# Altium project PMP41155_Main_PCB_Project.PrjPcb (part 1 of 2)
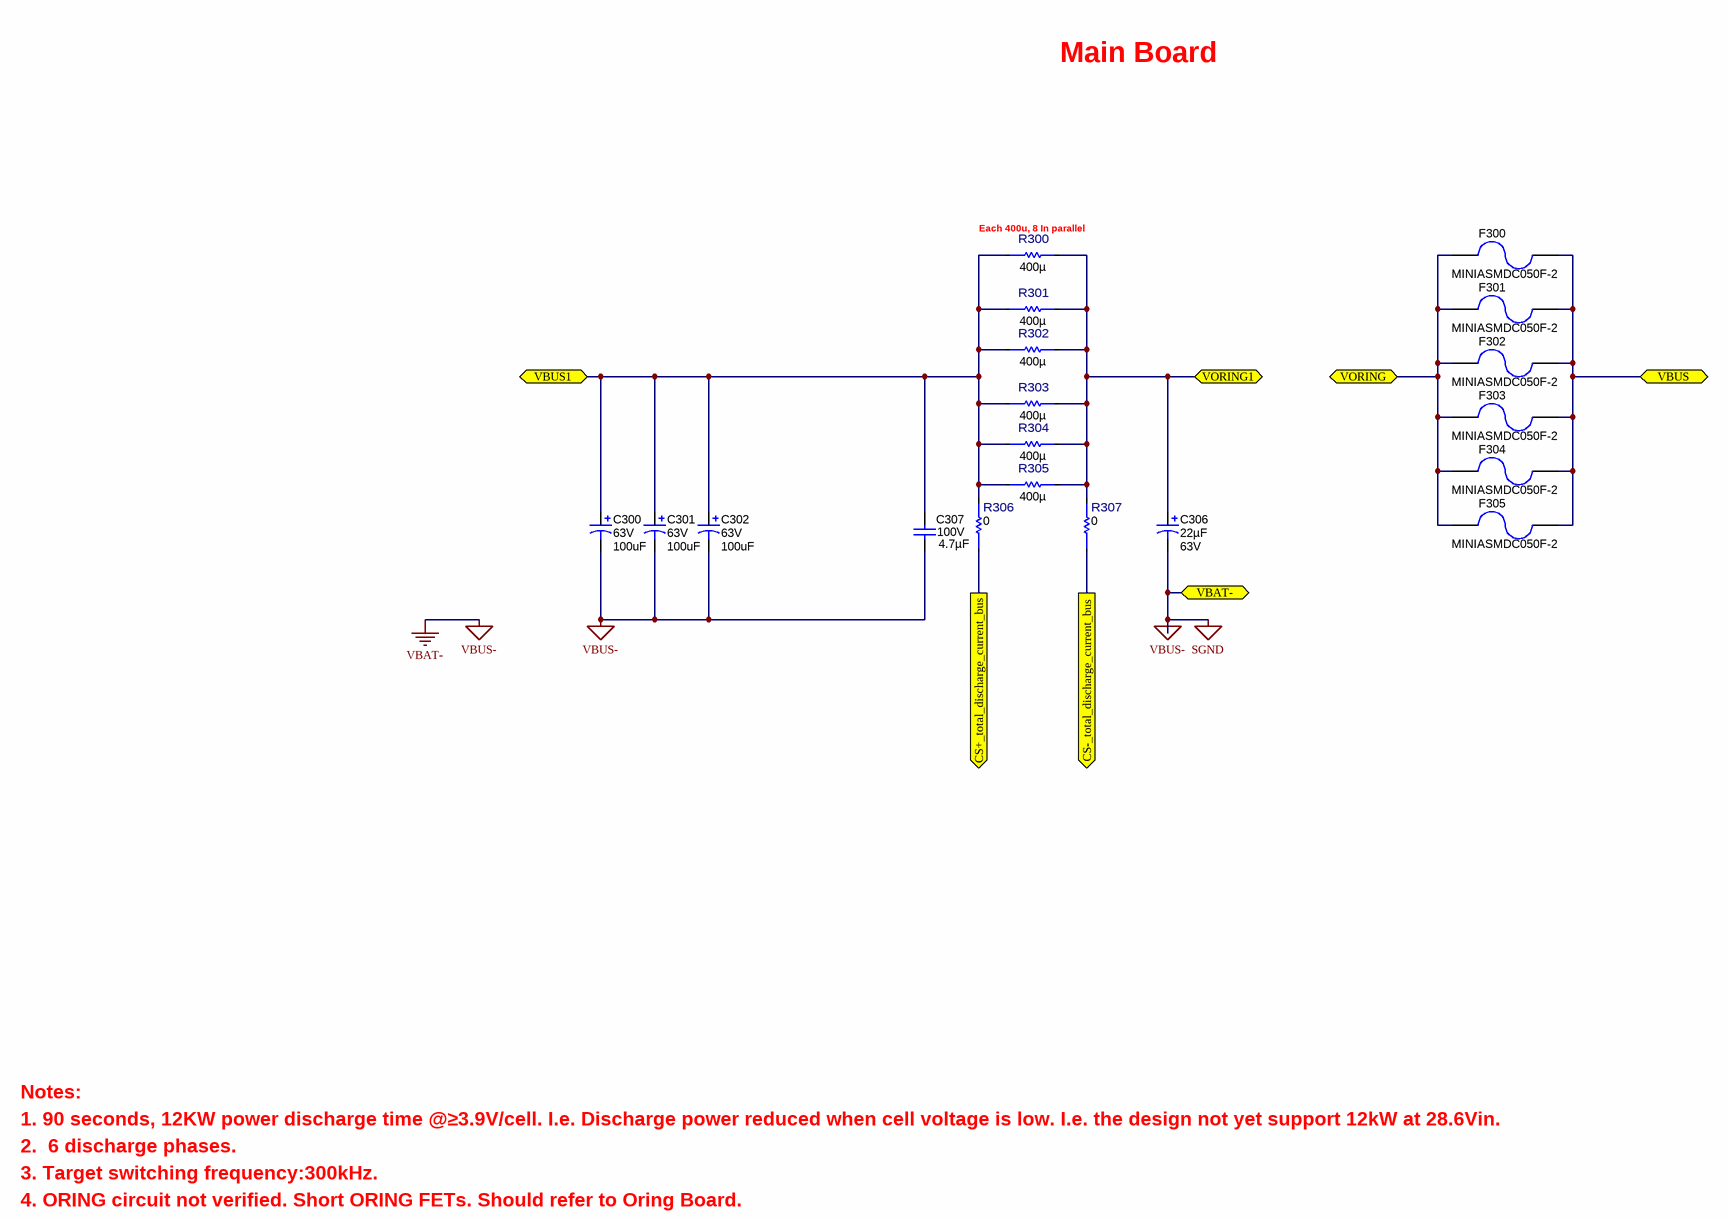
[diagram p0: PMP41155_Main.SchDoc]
CopyrightYear: 2025; PCB_Layout: Richard Yin; PCB_Rev: E1; PRJ_Customer: Public Release; PRJ_Engineer: Richard Yin; PRJ_Number: PMP41155_Main; PRJ_Title: Change in menu Project|Project Options|Parameters; SCH_Rev: E1; TechSupport: http://www.ti.com/support; TID: N/A
5 sheets, 249 parts. Net scope: flat (ports and power ports of the same name join across sheets).
Board file: PMP41155_Main.PcbDoc
Sheets:
  PMP41155_Main.SchDoc
  PMP41155_Main_Control 2.SchDoc
  PMP41155_Main_Control 1.SchDoc
  PMP41155_Main_Control.SchDoc
  PMP41155_Main_Connection.SchDoc

## Sheet PMP41155_Main.SchDoc
size 431 x 279 mm; Date: Not shown in title block; ApprovedBy: Not shown in title block; CheckedBy: Not shown in title block; Author: Not shown in title block; CompanyName: Not shown in title block; Engineer: Not shown in title block; Organization: Not shown in title block; Address1: Not shown in title block; Address2: Not shown in title block; Address3: Not shown in title block; Address4: Not shown in title block; DocumentNumber: 1; Revision: Use project parameter SCH_Rev; SheetNumber: 1; SheetTotal: 5; PageSetup: Record=PageOptions¦CenterHorizontal=True¦CenterVertical=True¦PrintScale=1.00¦XCorrection=1.00¦YCorrection=1.00¦PrintKind=0¦BorderSize=5000000¦LeftOffset=0¦BottomOffset=0¦Orientation=2¦PaperLength=1000¦PaperWidth=1000¦Scale=100¦PaperSource=15¦PrintQuality=600¦MediaType=1¦DitherType=10¦PaperKind=Letter¦PrintScaleMode=1

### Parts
C300  VDC_V: 63V  ValueDisplayed: 100uF  [CAPSMT_62_KE0]  (hidden comment: EMVY630ATR101MKE0S)
C301  VDC_V: 63V  ValueDisplayed: 100uF  [CAPSMT_62_KE0]  (hidden comment: EMVY630ATR101MKE0S)
C302  VDC_V: 63V  ValueDisplayed: 100uF  [CAPSMT_62_KE0]  (hidden comment: EMVY630ATR101MKE0S)
C306  ValueDisplayed: 22µF  Value2: 63V  [SM_RADIAL_D]  (hidden comment: 63PFV22M6.3X8)
C307  ValueDisplayed: 4.7µF  Value2: 100V  [1206_180]  (hidden comment: GRJ31CC72A475KE01L)
F300  MINIASMDC050F-2  [1812]
F301  MINIASMDC050F-2  [1812]
F302  MINIASMDC050F-2  [1812]
F303  MINIASMDC050F-2  [1812]
F304  MINIASMDC050F-2  [1812]
F305  MINIASMDC050F-2  [1812]
R300  value 400µ  [FP-PU3921FKNP90U4L_3921-MFG]  (hidden comment: PU3921FKNP90U4L)
R301  value 400µ  [FP-PU3921FKNP90U4L_3921-MFG]  (hidden comment: PU3921FKNP90U4L)
R302  value 400µ  [FP-PU3921FKNP90U4L_3921-MFG]  (hidden comment: PU3921FKNP90U4L)
R303  value 400µ  [FP-PU3921FKNP90U4L_3921-MFG]  (hidden comment: PU3921FKNP90U4L)
R304  value 400µ  [FP-PU3921FKNP90U4L_3921-MFG]  (hidden comment: PU3921FKNP90U4L)
R305  value 400µ  [FP-PU3921FKNP90U4L_3921-MFG]  (hidden comment: PU3921FKNP90U4L)
R306  Res_ohm: 0  [FP-RC0603JR-130RP_0603-MFG]  (hidden comment: RC0603JR-130RP)
R307  Res_ohm: 0  [FP-RC0603JR-130RP_0603-MFG]  (hidden comment: RC0603JR-130RP)

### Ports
CS+_total_discharge_current_bus (out), CS-_total_discharge_current_bus (out), VBAT- (bidir), VBUS1 (bidir), VBUS (bidir), VORING1 (bidir), VORING (bidir)

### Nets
SGND: C300.2(-) C301.2(-) C302.2(-) C306.2(-) C307.2 ; port VBAT-  [also labelled VBAT-, VBUS-]
CS+_total_discharge_current_bus: R306.1 ; port CS+_total_discharge_current_bus
CS-_total_discharge_current_bus: R307.1 ; port CS-_total_discharge_current_bus
VBUS: F300.1 F301.1 F302.1 F303.1 F304.1 F305.1 ; port VBUS
VBUS1: C300.1(+) C301.1(+) C302.1(+) C307.1 R300.1 R301.1 R302.1 R303.1 R304.1 R305.1 R306.2 ; port VBUS1
VORING: F300.2 F301.2 F302.2 F303.2 F304.2 F305.2 ; port VORING
VORING1: C306.1(+) R300.2 R301.2 R302.2 R303.2 R304.2 R305.2 R307.2 ; port VORING1

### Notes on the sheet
- Main Board
- (near R300) Each 400u, 8 In parallel
- Notes:
- 2.  6 discharge phases.
- 1. 90 seconds, 12KW power discharge time @≥3.9V/cell. I.e. Discharge power reduced when cell voltage is low. I.e. the design not yet support 12kW at 28.6Vin.
- 3. Target switching frequency:300kHz.
- 4. ORING circuit not verified. Short ORING FETs. Should refer to Oring Board.

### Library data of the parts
C300-C302 = CMP-0011370-2: CAP, AL, 100 uF, 63 V, +/- 20%, 0.19 ohm, SMD; Manufacturer: Chemi-Con; TaMin_C: -55°C; ESR_ohm: 0.19; Polarized: Y; SizeAreaWB_mm2: 225; U/M: EA; Value: 100uF; TaMax_C: 105°C; SizeZ_mm: 13.5; SizeX_mm: 13; Cap_Case: KE0; SizeArea_mm2: 169; CompType: Capacitor; Cap_F: 100µF; IRMS_A: 500mA; AEC Category: Q200
C306 = EEE-FK1H220P: CAP ALUM POLY HYB 22UF 63V SMD; Manufacturer: Rubycon; Polarized: Y; CompType: Capacitor; Cap_F: 0.000022; Tolerance_%: 20; Value1: 0.88 ohm; VDC_V: 63; Cap_Case: D; SizeAreaWB_mm2: 84.28; SizeArea_mm2: 51.48; SizeX_mm: 7.8; SizeY_mm: 6.6; SizeZ_mm: 5.4; Green_Lifecycle: Active; Green_REACh: Passed
C307 = C3216X6S1H475K160AB: CAP CER 4.7UF 100V X7S 1206; Polarized: N; CompType: Capacitor; U/M: EA; Cap_F: 0.0000047; Tolerance_%: 10; VDC_V: 100; TaMin_C: -55; TaMax_C: 105; Cap_Case: 1206; SizeArea_mm2: 5.12; SizeAreaWB_mm2: 10.92; SizeX_mm: 3.2; SizeY_mm: 1.6; SizeZ_mm: 1.8; AEC Category: Q200
F300-F305 = CMP-0003593-3: Fuse, Resettable, 100 A, 24 VDC, SMD; Manufacturer: Littelfuse; Irating_A: 100A; SizeAreaWB_mm2: 23.1; SizeZ_mm: 1.35; SizeX_mm: 4.5; SizeY_mm: 3.2; SizeArea_mm2: 14.4; VDC_V: 24V
R300-R305 = CMP-0096319-1: 400 µOhms ±1% 9W Chip Resistor Nonstandard Automotive AEC-Q200, Current Sense, Moisture Resistant Metal Element; Manufacturer: YAGEO; AEC Qualified: Yes; TempCo: 175ppm/°C; SizeZ_mm: 1.81mm; AEC Grade: Grade 0; Standoff Height: 0.37mm
R306 R307 = CMP-0120804-1: Resistor Thick Film 0603 Jumper 0 Ohm ±5% 1/10W Molded Paper T/R; Manufacturer: Yageo; AEC Qualified: No; Power_W: 100mW; SizeZ_mm: 0.55mm; VDC_V: 75V; Value: 0

## Sheet PMP41155_Main_Control 2.SchDoc
size 431 x 279 mm; Date: Not shown in title block; ApprovedBy: Not shown in title block; CheckedBy: Not shown in title block; Author: Not shown in title block; CompanyName: Not shown in title block; Engineer: Not shown in title block; Organization: Not shown in title block; Address1: Not shown in title block; Address2: Not shown in title block; Address3: Not shown in title block; Address4: Not shown in title block; DocumentNumber: 2; Revision: Use project parameter SCH_Rev; SheetNumber: 2; SheetTotal: 5; PageSetup: Record=PageOptions¦CenterHorizontal=True¦CenterVertical=True¦PrintScale=1.00¦XCorrection=1.00¦YCorrection=1.00¦PrintKind=0¦BorderSize=5000000¦LeftOffset=0¦BottomOffset=0¦Orientation=2¦PaperLength=1000¦PaperWidth=1000¦Scale=100¦PaperSource=15¦PrintQuality=600¦MediaType=1¦DitherType=10¦PaperKind=Letter¦PrintScaleMode=1
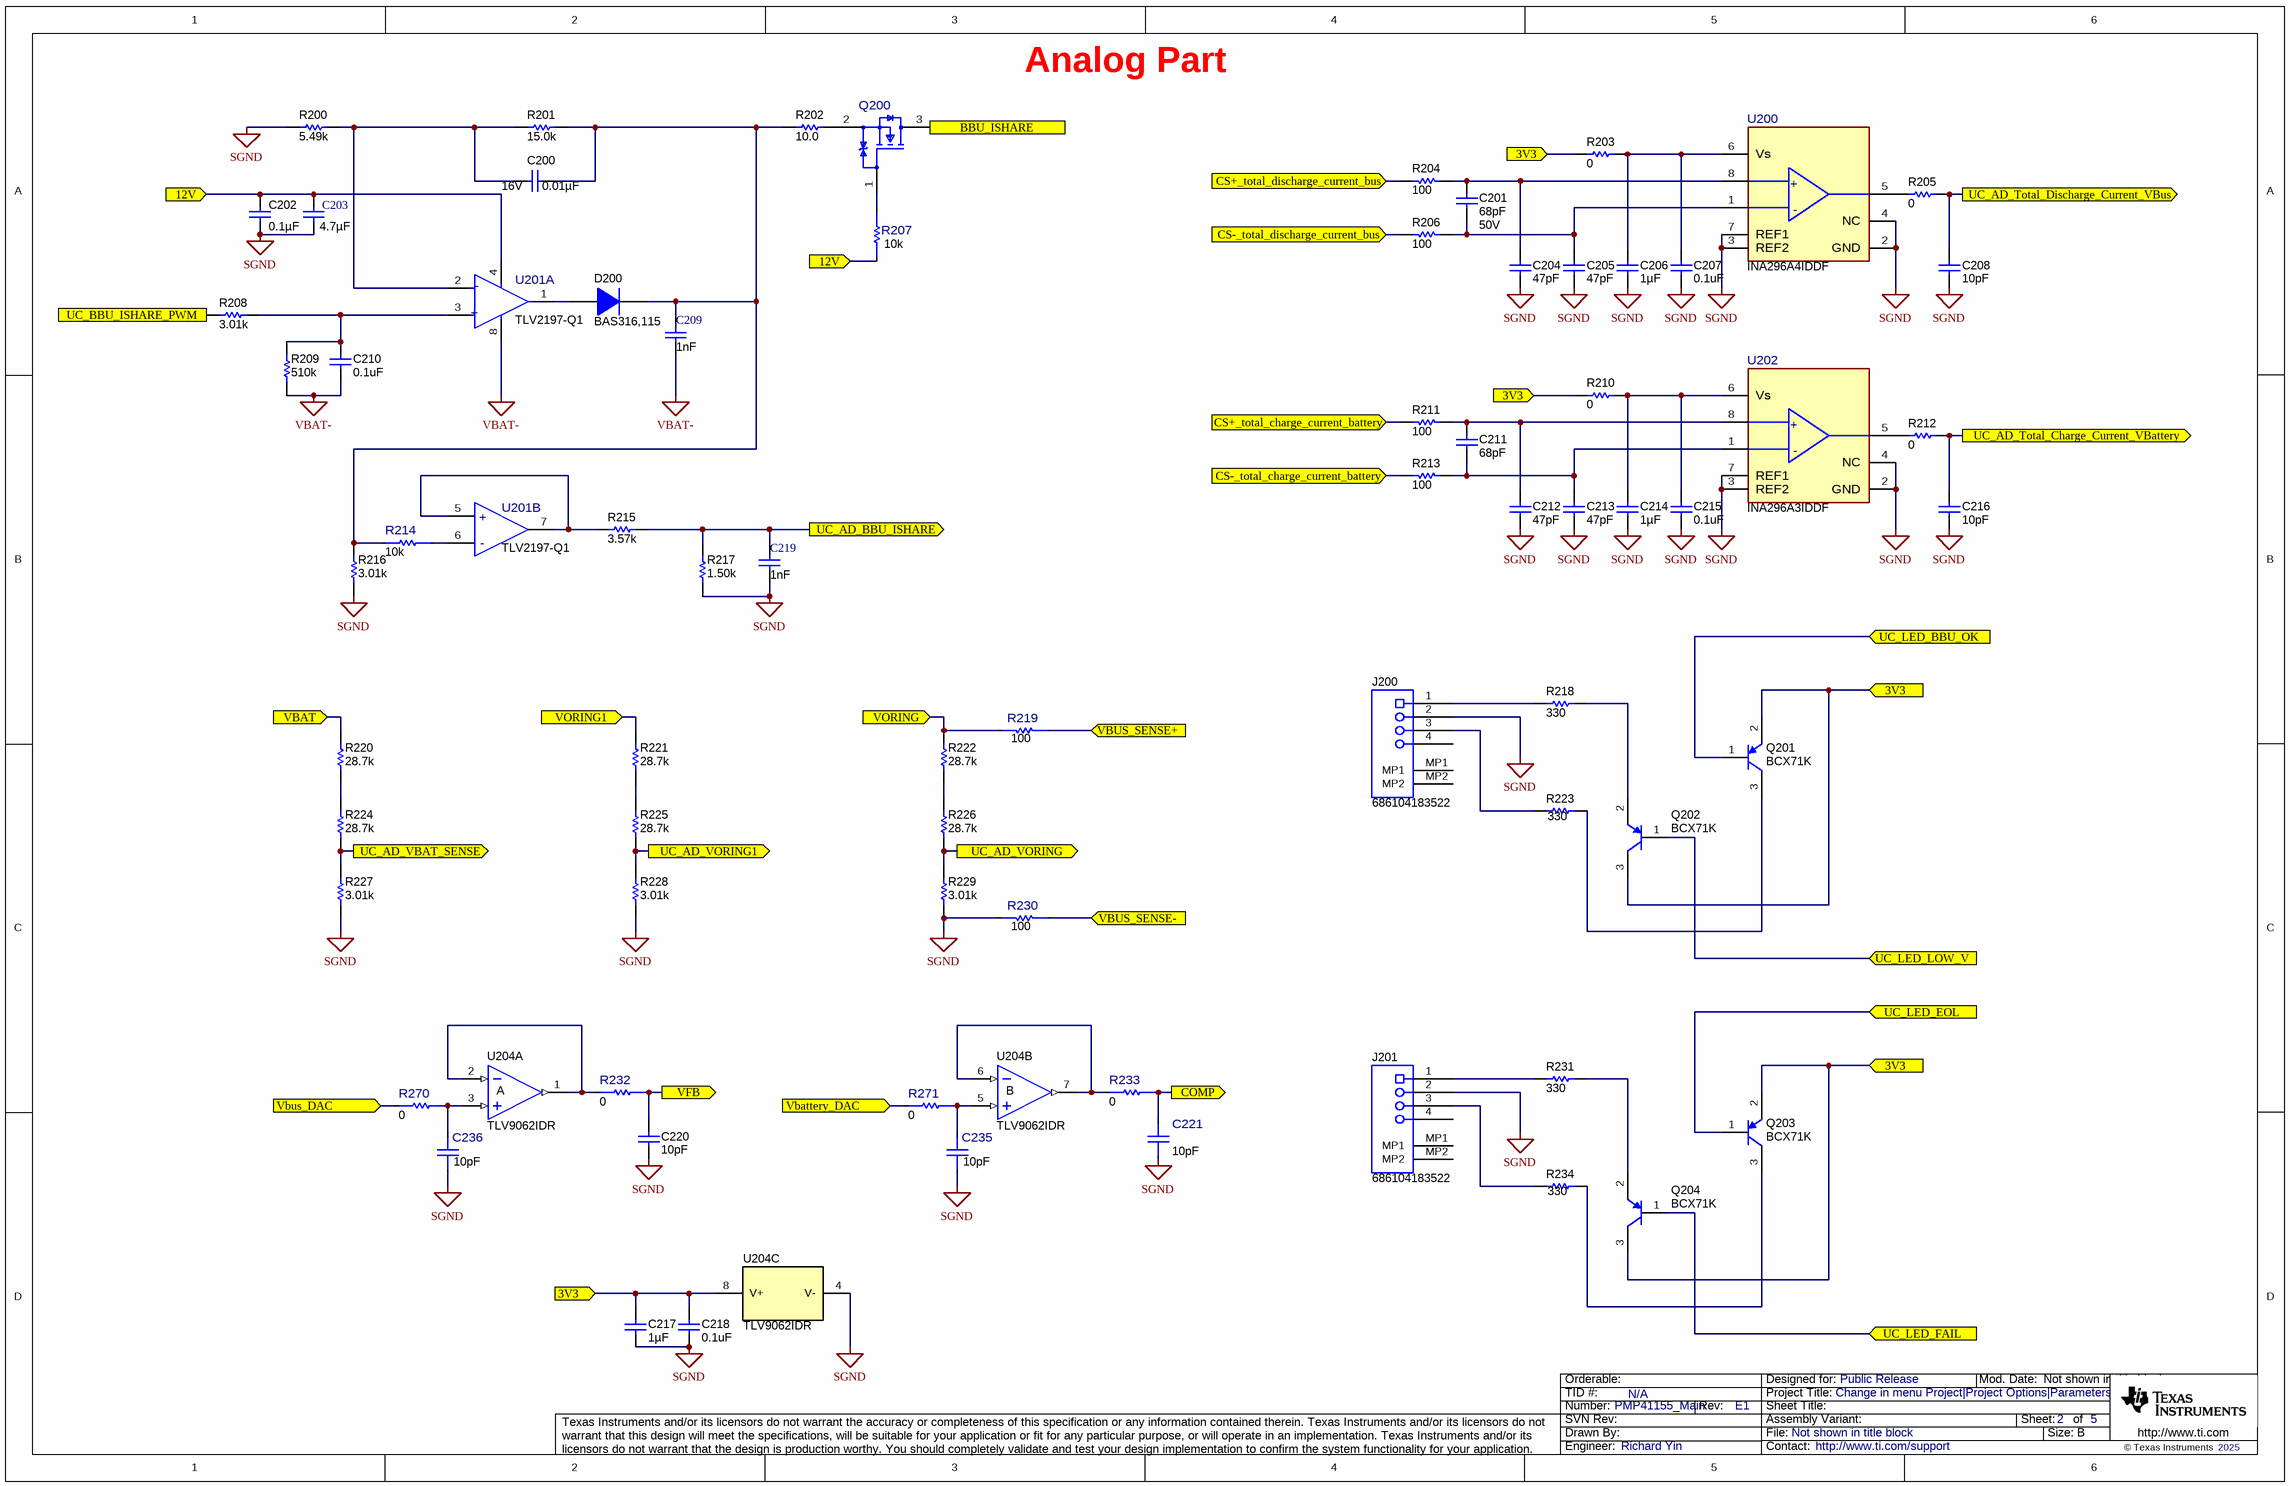
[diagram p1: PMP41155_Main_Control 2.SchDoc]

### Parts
C200  VDC_V: 16V  ValueDisplayed: 0.01µF  [0402]  (hidden comment: C0402C103K4RACTU)
C201  ValueDisplayed: 68pF  Value2: 50V  [0603]  (hidden comment: 06035A680JAT2A)
C202  ValueDisplayed: 0.1µF  [0603]  (hidden comment: 0603YC104K4T4A)
C203  Cap_F: 4.7µF  [WCAP-CSGP_0805_L2W1.25H1.25]  (hidden comment: 885012107013)
C204  ValueDisplayed: 47pF  [0402]  (hidden comment: GRM1555C1H470FA01D)
C205  ValueDisplayed: 47pF  [0402]  (hidden comment: GRM1555C1H470FA01D)
C206  ValueDisplayed: 1µF  [0603]  (hidden comment: C1608X7R1C105K080AC)
C207  ValueDisplayed: 0.1uF  [0402]  (hidden comment: GRM155R70J104KA01D)
C208  ValueDisplayed: 10pF  [0603]  (hidden comment: C0603C100F5GAC7867)
C209  Cap_F: 1nF  [WCAP-CSGP_0402_L1W0.5H0.5]  (hidden comment: 885012205061)
C210  ValueDisplayed: 0.1uF  [0402]  (hidden comment: GRM155R70J104KA01D)
C211  ValueDisplayed: 68pF  [0603]  (hidden comment: 06035A680JAT2A)
C212  ValueDisplayed: 47pF  [0402]  (hidden comment: GRM1555C1H470FA01D)
C213  ValueDisplayed: 47pF  [0402]  (hidden comment: GRM1555C1H470FA01D)
C214  ValueDisplayed: 1µF  [0603]  (hidden comment: C1608X7R1C105K080AC)
C215  ValueDisplayed: 0.1uF  [0402]  (hidden comment: GRM155R70J104KA01D)
C216  ValueDisplayed: 10pF  [0603]  (hidden comment: C0603C100F5GAC7867)
C217  Cap_F: 1µF  [0603]  (hidden comment: GCM188R71C105KA64J)
C218  ValueDisplayed: 0.1uF  [0402]  (hidden comment: GRM155R70J104KA01D)
C219  Cap_F: 1nF  [WCAP-CSGP_0402_L1W0.5H0.5]  (hidden comment: 885012205061)
C220  ValueDisplayed: 10pF  [0603]  (hidden comment: C0603C100F5GAC7867)
C221  ValueDisplayed: 10pF  [FP-06035C100KAT2A_0603-MFG]  (hidden comment: 06035C100KAT2A)
C235  ValueDisplayed: 10pF  [FP-06035C100KAT2A_0603-MFG]  (hidden comment: 06035C100KAT2A)
C236  ValueDisplayed: 10pF  [FP-06035C100KAT2A_0603-MFG]  (hidden comment: 06035C100KAT2A)
D200  BAS316,115  [SOD-323]
J200  686104183522  [Wurth_686104183522]
J201  686104183522  [Wurth_686104183522]
Q200  2N7002KL3A-TP  [FP-2N7002KL3A-TP_DFN3-MFG]  (value not drawn)
Q201  BCX71K  [SOT-23]
Q202  BCX71K  [SOT-23]
Q203  BCX71K  [SOT-23]
Q204  BCX71K  [SOT-23]
R200  ValueDisplayed: 5.49k  [0402]  (hidden comment: CRCW04025K49FKED)
R201  ValueDisplayed: 15.0k  [0402]  (hidden comment: CRCW040215K0FKED)
R202  ValueDisplayed: 10.0  [0402]  (hidden comment: MCR01MZPF10R0)
R203  ValueDisplayed: 0  [0603]  (hidden comment: RC0603JR-070RL)
R204  ValueDisplayed: 100  [0603]  (hidden comment: RC0603FR-07100RL)
R205  ValueDisplayed: 0  [0603]  (hidden comment: RC0603JR-070RL)
R206  ValueDisplayed: 100  [0603]  (hidden comment: RC0603FR-07100RL)
R207  Res_ohm: 10k  [FP-ERJ-U02F1002X_0402-MFG]  (hidden comment: ERJ-U02F1002X)
R208  ValueDisplayed: 3.01k  [0402]  (hidden comment: CRCW04023K01FKED)
R209  ValueDisplayed: 510k  [0603]  (hidden comment: RC0603FR-07510KL)
R210  ValueDisplayed: 0  [0603]  (hidden comment: RC0603JR-070RL)
R211  ValueDisplayed: 100  [0603]  (hidden comment: RC0603FR-07100RL)
R212  ValueDisplayed: 0  [0603]  (hidden comment: RC0603JR-070RL)
R213  ValueDisplayed: 100  [0603]  (hidden comment: RC0603FR-07100RL)
R214  Res_ohm: 10k  [FP-ERJ-U02F1002X_0402-MFG]  (hidden comment: ERJ-U02F1002X)
R215  ValueDisplayed: 3.57k  [0402]  (hidden comment: CRCW04023K57FKED)
R216  ValueDisplayed: 3.01k  [0402]  (hidden comment: CRCW04023K01FKED)
R217  ValueDisplayed: 1.50k  [0402]  (hidden comment: ERJ-2RKF1501X)
R218  ValueDisplayed: 330  [0402]  (hidden comment: CRCW0402330RJNED)
R219  Res_ohm: 100  [FP-RK73H1JTTD1000F_0603-MFG]  (hidden comment: RK73H1JTTD1000F)
R220  ValueDisplayed: 28.7k  [0603]  (hidden comment: CRCW060328K7FKEA)
R221  ValueDisplayed: 28.7k  [0603]  (hidden comment: RC0603FR-0728K7L)
R222  ValueDisplayed: 28.7k  [0603]  (hidden comment: CRCW060328K7FKEA)
R223  ValueDisplayed: 330  [0402]  (hidden comment: CRCW0402330RJNED)
R224  ValueDisplayed: 28.7k  [0603]  (hidden comment: CRCW060328K7FKEA)
R225  ValueDisplayed: 28.7k  [0603]  (hidden comment: CRCW060328K7FKEA)
R226  ValueDisplayed: 28.7k  [0603]  (hidden comment: RC0603FR-0728K7L)
R227  ValueDisplayed: 3.01k  [0603]  (hidden comment: CRCW06033K01FKEA)
R228  ValueDisplayed: 3.01k  [0603]  (hidden comment: RT0603BRD073K01L)
R229  ValueDisplayed: 3.01k  [0603]  (hidden comment: RT0603BRD073K01L)
R230  Res_ohm: 100  [FP-RK73H1JTTD1000F_0603-MFG]  (hidden comment: RK73H1JTTD1000F)
R231  ValueDisplayed: 330  [0402]  (hidden comment: CRCW0402330RJNED)
R232  Res_ohm: 0  [FP-RC0603JR-130RP_0603-MFG]  (hidden comment: RC0603JR-130RP)
R233  Res_ohm: 0  [FP-RC0603JR-130RP_0603-MFG]  (hidden comment: RC0603JR-130RP)
R234  ValueDisplayed: 330  [0402]  (hidden comment: CRCW0402330RJNED)
R270  Res_ohm: 0  [FP-RC0603JR-130RP_0603-MFG]  (hidden comment: RC0603JR-130RP)
R271  Res_ohm: 0  [FP-RC0603JR-130RP_0603-MFG]  (hidden comment: RC0603JR-130RP)
U200  INA296A4IDDF  [DDF0008A-MFG]
U201  TLV2197-Q1  [DGK0008A-MFG]  (parts A,B of 2)
U202  INA296A3IDDF  [DDF0008A-MFG]
U204  TLV9062IDR  [D0008A_N]  (parts A,B,C of 3)

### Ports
3V3 (in), 12V (in), BBU_ISHARE (out), COMP (out), CS+_total_charge_current_battery (in), CS+_total_discharge_current_bus (in), CS-_total_charge_current_battery (in), CS-_total_discharge_current_bus (in), UC_AD_BBU_ISHARE (out), UC_AD_Total_Charge_Current_VBattery (out), UC_AD_Total_Discharge_Current_VBus (out), UC_AD_VBAT_SENSE (out), UC_AD_VORING1 (out), UC_AD_VORING (out), UC_BBU_ISHARE_PWM (in), UC_LED_BBU_OK (in), UC_LED_EOL (in), UC_LED_FAIL (in), UC_LED_LOW_V (in), VBAT (in), Vbattery_DAC (in), Vbus_DAC (in), VBUS_SENSE+ (in), VBUS_SENSE- (in), VFB (out), VORING1 (in), VORING (in)

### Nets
SGND: C202.2 C203.1 C204.2 C205.2 C206.2 C207.2 C208.2 C209.1 C210.2 C212.2 C213.2 C214.2 C215.2 C216.2 C217.2 C218.2 C219.1 C220.2 C221.1 C235.1 C236.1 J200.2 J201.2 R200.1 R209.1 R216.1 R217.1 R227.1 R228.1 R229.1 R230.2 U200.2(GND) U200.3(REF2) U200.4(NC) U200.7(REF1) U201.8(V+) U202.2(GND) U202.3(REF2) U202.4(NC) U202.7(REF1) U204.4(V-)  [also labelled VBAT-]
3V3: C217.1 C218.1 Q201.2(E) Q202.3(C) Q203.2(E) Q204.3(C) R203.1 R210.1 U204.8(V+) ; port 3V3
12V: C202.1 C203.2 R207.1 U201.4(V-) ; port 12V
BBU_ISHARE: Q200.3(D) ; port BBU_ISHARE
COMP: C221.2 R233.1 ; port COMP
CS+_total_charge_current_battery: R211.2 ; port CS+_total_charge_current_battery
CS+_total_discharge_current_bus: R204.2 ; port CS+_total_discharge_current_bus
CS-_total_charge_current_battery: R213.2 ; port CS-_total_charge_current_battery
CS-_total_discharge_current_bus: R206.2 ; port CS-_total_discharge_current_bus
UC_AD_BBU_ISHARE: C219.2 R215.2 R217.2 ; port UC_AD_BBU_ISHARE
UC_AD_Total_Charge_Current_VBattery: C216.1 R212.2 ; port UC_AD_Total_Charge_Current_VBattery
UC_AD_Total_Discharge_Current_VBus: C208.1 R205.2 ; port UC_AD_Total_Discharge_Current_VBus
UC_AD_VBAT_SENSE: R224.1 R227.2 ; port UC_AD_VBAT_SENSE
UC_AD_VORING: R226.1 R229.2 ; port UC_AD_VORING
UC_AD_VORING1: R225.1 R228.2 ; port UC_AD_VORING1
UC_BBU_ISHARE_PWM: R208.1 ; port UC_BBU_ISHARE_PWM
UC_LED_BBU_OK: Q201.1(B) ; port UC_LED_BBU_OK
UC_LED_EOL: Q203.1(B) ; port UC_LED_EOL
UC_LED_FAIL: Q204.1(B) ; port UC_LED_FAIL
UC_LED_LOW_V: Q202.1(B) ; port UC_LED_LOW_V
VBAT: R220.2 ; port VBAT
Vbattery_DAC: R271.2 ; port Vbattery_DAC
Vbus_DAC: R270.2 ; port Vbus_DAC
VBUS_SENSE+: R219.1 ; port VBUS_SENSE+
VBUS_SENSE-: R230.1 ; port VBUS_SENSE-
VFB: C220.1 R232.1 ; port VFB
VORING: R219.2 R222.2 ; port VORING
VORING1: R221.2 ; port VORING1
NetC200_1: C200.1 C209.2 D200.1(K) R201.2 R202.2 R214.2 R216.2
NetC200_2: C200.2 R200.2 R201.1 U201.2(-IN_A)
NetC201_1: C201.1 C204.1 R204.1 U200.8(IN+)
NetC201_2: C201.2 C205.1 R206.1 U200.1(IN-)
NetC206_1: C206.1 C207.1 R203.2 U200.6(Vs)
NetC210_1: C210.1 R208.2 R209.2 U201.3(+IN_A)
NetC211_1: C211.1 C212.1 R211.1 U202.8(IN+)
NetC211_2: C211.2 C213.1 R213.1 U202.1(IN-)
NetC214_1: C214.1 C215.1 R210.2 U202.6(Vs)
NetC235_2: C235.2 R271.1 U204.5(IN+)
NetC236_2: C236.2 R270.1 U204.3(IN+)
NetD200_2: D200.2(A) U201.1(OUT_A)
NetJ200_1: J200.1 R218.1
NetJ200_3: J200.3 R223.1
NetJ201_1: J201.1 R231.1
NetJ201_3: J201.3 R234.1
NetQ200_1: Q200.1(G) R207.2
NetQ200_2: Q200.2(S) R202.1
NetQ201_3: Q201.3(C) R223.2
NetQ202_2: Q202.2(E) R218.2
NetQ203_3: Q203.3(C) R234.2
NetQ204_2: Q204.2(E) R231.2
NetR205_1: R205.1 U200.5(OUT)
NetR212_1: R212.1 U202.5(OUT)
NetR214_1: R214.1 U201.6(-IN_B)
NetR215_1: R215.1 U201.5(+IN_B) U201.7(OUT_B)
NetR220_1: R220.1 R224.2
NetR221_1: R221.1 R225.2
NetR222_1: R222.1 R226.2
NetR232_2: R232.2 U204.1(OUT) U204.2(IN-)
NetR233_2: R233.2 U204.6(IN-) U204.7(OUT)

Not connected (* = marked no-connect by the designer): J200 4 MP1 MP2; J201 4 MP1 MP2

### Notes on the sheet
- Analog Part

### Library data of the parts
C200 = CMP-0078218-1: CAP, CERM, 0.01 µF, 16 V,+/- 10%, X7R, 0402; Manufacturer: Kemet; TaMin_C: -55°C; Polarized: N; Green_Lifecycle: Active; SizeAreaWB_mm2: 3; Green_REACh: Passed; U/M: EA; Value: 0.01uF; TaMax_C: 125°C; SizeZ_mm: 0.6; SizeX_mm: 1; SizeY_mm: 0.5; Cap_F: 10nF; AEC Category: Q200
C201 = 06035A680JAT2A: CAP, CERM, 68 pF, 50 V,+/- 5%, C0G/NP0, 0603; Manufacturer: AVX; Polarized: N; CompType: Capacitor; Value: 68pF; U/M: EA; Cap_F: 0.000000000068; Tolerance_%: 5; ESR_ohm: 0.144; Value1: 0.144 ohm; VDC_V: 50; TaMin_C: -55; TaMax_C: 125; SizeArea_mm2: 1.28; SizeAreaWB_mm2: 4.68; SizeX_mm: 1.6; SizeY_mm: 0.8; SizeZ_mm: 1; AEC Category: Q200; Green_Lifecycle: Active; Green_REACh: Passed
C202 = CMP-0083626-1: CAP, CERM, 0.1 µF, 16 V,+/- 10%, X7R, AEC-Q200 Grade 1, 0603; Manufacturer: AVX; Polarized: N; Value: 0.1uF; U/M: EA; Cap_F: 100nF; VDC_V: 16V; TaMin_C: -55°C; TaMax_C: 125°C; SizeAreaWB_mm2: 4.68; SizeArea_mm2: 1.28; AEC Qualified: Y; AEC Category: Q200; SizeZ_mm: 1; SizeY_mm: 0.8; SizeX_mm: 1.6
C203 = CMP-0104520-1: WCAP-CSGP Multilayer Ceramic Chip Capacitor, General Purpose, size 0805, X5R, 4.7µF, 16VDC; Manufacturer: Wurth Elektronik; Capacitance Tolerance: +/-20%; Case/Size Code: 0805; Dissipation Factor: 10%; Insulation Resistance: 0.02GOhm; Rated Voltage (DC): 16V; Technical Reference: X5R0805475M016DFCT10000
C204 C205 C212 C213 = GRM1555C1H470FA01D: CAP, CERM, 47 pF, 50 V,+/- 1%, C0G/NP0, 0402; Manufacturer: MuRata; Polarized: N; CompType: Capacitor; Value: 47pF; U/M: EA; Cap_F: 0.000000000047; Tolerance_%: 1; VDC_V: 50; Value2: 50V; TaMin_C: -55; TaMax_C: 125; SizeArea_mm2: 0.5; SizeAreaWB_mm2: 3; SizeZ_mm: 0.6; AEC Category: Q200; Green_Lifecycle: Active; Green_REACh: Passed
C206 C214 = C1608X7R1C105K080AC: CAP, CERM, 1 µF, 16 V,+/- 10%, X7R, 0603; Manufacturer: TDK; Polarized: N; CompType: Capacitor; Value: 1uF; U/M: EA; Cap_F: 0.000001; Tolerance_%: 10; ESR_ohm: 0.0057; Value1: 0.0057 ohm; VDC_V: 16; Value2: 16V; TaMin_C: -55; TaMax_C: 125; SizeArea_mm2: 1.28; SizeAreaWB_mm2: 4.68; SizeX_mm: 1.6; SizeY_mm: 0.8; SizeZ_mm: 1; AEC Category: Q200; Green_Lifecycle: Active; Green_REACh: Passed
C207 C215 = GRM155R70J104KA01D: CAP, CERM, 0.1uF, 6.3V, +/-10%, X7R, 0402; Manufacturer: MuRata; Polarized: N; CompType: Capacitor; U/M: EA; Cap_F: 0.0000001; Tolerance_%: 10; Value1: Unknown; VDC_V: 6.3; TaMin_C: -55; TaMax_C: 125
C208 C216 C220 = C0603C100F5GAC7867: CAP, CERM, 10 pF, 50 V,+/- 1%, C0G/NP0, 0603; Manufacturer: Kemet; Polarized: N; CompType: Capacitor; Value: 10pF; U/M: EA; Cap_F: 0.00000000001; Tolerance_%: 1; VDC_V: 50; Value2: 50V; TaMin_C: -55; TaMax_C: 125; SizeArea_mm2: 1.28; SizeAreaWB_mm2: 4.68; SizeX_mm: 1.6; SizeY_mm: 0.8; AEC Category: Q200; Green_Lifecycle: Active; Green_REACh: Passed
C209 C219 = CMP-0115372-1: WCAP-CSGP Multilayer Ceramic Chip Capacitor, General Purpose, size 0402, X7R, 1nF, 50VDC; Manufacturer: Wurth Elektronik; Capacitance Tolerance: +/-10%; Case/Size Code: 0402; Dissipation Factor: 2.5%; Insulation Resistance: 10GOhm; Rated Voltage (DC): 50V; Technical Reference: X7R0402102K050DFCT10000
C210 C218 = CMP-0006623-2: CAP, CERM, 0.1 uF, 6.3 V, +/- 10%, X7R, 0402; Manufacturer: MuRata; Polarized: N; Value: 0.1uF; U/M: EA; Cap_F: 100nF; Value1: Unknown; VDC_V: 6.3V; TaMin_C: -55°C; TaMax_C: 125°C; SizeAreaWB_mm2: 3; SizeZ_mm: 0.6; SizeX_mm: 1; SizeY_mm: 0.5; AEC Category: Q200
C211 = 06035A680JAT2A: CAP, CERM, 68 pF, 50 V,+/- 5%, C0G/NP0, 0603; Manufacturer: AVX; Polarized: N; CompType: Capacitor; Value: 68pF; U/M: EA; Cap_F: 0.000000000068; Tolerance_%: 5; ESR_ohm: 0.144; Value1: 0.144 ohm; VDC_V: 50; Value2: 50V; TaMin_C: -55; TaMax_C: 125; SizeArea_mm2: 1.28; SizeAreaWB_mm2: 4.68; SizeX_mm: 1.6; SizeY_mm: 0.8; SizeZ_mm: 1; AEC Category: Q200; Green_Lifecycle: Active; Green_REACh: Passed
C217 = CMP-0079154-1: CAP, CERM, 1 µF, 16 V,+/- 10%, X7R, AEC-Q200 Grade 1, 0603; Manufacturer: MuRata; SizeAreaWB_mm2: 4.68; SizeArea_mm2: 1.28; AEC Qualified: Y; AEC Category: Q200; Value: 1uF; TaMax_C: 125°C; SizeZ_mm: 1; Polarized: N; TaMin_C: -55°C; VDC_V: 16V; SizeY_mm: 0.8; U/M: EA; SizeX_mm: 1.6
C221 C235 C236 = CMP-0046668-1: 10 pF ±10% 50V Ceramic Capacitor X7R 0603 (1608 Metric); Manufacturer: KYOCERA AVX; Value: 10pF; TempCo: 15%; SizeZ_mm: 0.9mm; AEC Qualified: No
D200 = CMP-0029006-2: Diode, Ultrafast, 100 V, 0.25 A, SOD-323; Manufacturer: Nexperia; SizeY_mm: 1.35; Value1: 0.25A; SizeAreaWB_mm2: 8.695; SizeZ_mm: 1; Io_A: 250mA; Value2: 1.4V; SizeX_mm: 2.7; Green_REACh: Incomplete; TJmax_C: 150°C; Green_Lifecycle: Not Set; Vr_V: 100V; AEC Category: Q101; Value: 100V; SizeArea_mm2: 3.645
J200 J201 = CMP-0081506-1: FPC Connector, 1mm, 4 Pos, R/A, Tin, SMT; Manufacturer: Wurth Elektronik; Pitch_mm: 1; Gender: Female; Cert_UL: Y; Voltage_V: 50V; Current_A: 800mA; CompType: FFC or FPC
Q200 = CMP-0043768-1: N-Channel 60 V 260mA (Ta) 200mW Surface Mount DFN1006-3; Manufacturer: MCC; AEC Qualified: No; QgTyp_nC: 1.22nC @ 10V; Rdson45_ohm: 1.9; SizeZ_mm: 0.55mm; VdsMax_V: 1.2V; Vgs_V: 20V; ChMode: False; Drain To Source Breakdown Voltage: 60V; Input Capacitace At Vds: 21pF @ 30V; Number Of Channels: 1; Power_W: 0.2W; Pulse Drain Current: 1.3A; Reverse Recovery Charge: 3.6nC; Reverse Recovery Time: 16ns; Rthja Max: 600°C/W; Standoff Height: 0mm; Threshold Vgs Max: 2.5V; Threshold Vgs Min: 1V; TJmax_C: +150°C; Transconductance: 0.13S; Turn Off Delay Time: 20ns; Turn On Delay Time: 7ns; Typ Forward Diode Voltage: 0.9V
Q201-Q204 = CMP-0000319-2: Transistor, PNP, 45 V, 0.1 A, SOT-23; Manufacturer: Infineon Technologies; TaMax_C: 150°C; Value2: 630; Value1: 0.1 A; Vcesat1_V: 120mV; SizeX_mm: 2.5; SizeY_mm: 3; TaMin_C: -65°C; IcRated_A: 100mA; CompType: BJT; SizeZ_mm: 1.1; Value: 45 V; SizeArea_mm2: 7.5; NPN: 0; Vceo_V: 45V; PNP: 1; AEC Category: Q101; SizeAreaWB_mm2: 14; U/M: EA
R200 = CMP-0026466-2: RES, 5.49 k, 1%, 0.063 W, AEC-Q200 Grade 0, 0402; Manufacturer: Vishay-Dale; Power_W: 63mW; TempCo: 100 ppm/C; Value_Code: 5k49; Value: 5.49k; EIA_Code: E96; SizeX_mm: 1; SizeY_mm: 0.5; SizeZ_mm: 0.6; Value2: 0.063W; AEC Qualified: Y; VDC_V: 50V; AEC Category: Q200; AEC Grade: 0
R201 = CMP-0026027-3: RES, 15.0 k, 1%, 0.063 W, AEC-Q200 Grade 0, 0402; Manufacturer: Vishay-Dale; Power_W: 63mW; TempCo: 100 ppm/C; Value_Code: 15k0; Value: 15.0k; EIA_Code: E96; Res_ohm: 15k; SizeX_mm: 1; SizeY_mm: 0.5; SizeZ_mm: 0.6; Value2: 0.063W; AEC Qualified: Y; VDC_V: 50V; AEC Category: Q200; AEC Grade: 0
R202 = CMP-0026717-1: RES, 10.0, 1%, 0.063 W, 0402; Manufacturer: Rohm; Power_W: 63mW; TempCo: 100 ppm/C; Value_Code: 10R0; U/M: EA; Value: 10.0; EIA_Code: E96; Res_ohm: 10; SizeX_mm: 1; SizeY_mm: 0.5; SizeZ_mm: 0.6; Value2: 0.063W; AEC Qualified: N; VDC_V: 50V; AEC Category: Q200
R203 R205 R210 R212 = RC0603JR-070RL: RES, 0, 5%, 0.1 W, 0603; Manufacturer: Yageo America; CompType: Resistor; Value: 0; Value_Code: 0000; Tolerance_%: 5; Power_W: 0.1; Value2: 0.1W; VDC_V: 50; TempCo: 200 ppm/C; SizeArea_mm2: 1.28; SizeX_mm: 1.6; SizeY_mm: 0.8; SizeZ_mm: 1; EIA_Code: E24; U/M: EA; AEC Category: Q200; Green_Lifecycle: Active; Green_REACh: Passed
R204 R206 R211 R213 = RC0603FR-07100RL: RES, 100, 1%, 0.1 W, 0603; Manufacturer: Yageo America; CompType: Resistor; Value: 100; Value_Code: 100R; Tolerance_%: 1; Power_W: 0.1; Value2: 0.1W; VDC_V: 150; TempCo: 200 ppm/C; SizeArea_mm2: 1.28; SizeX_mm: 1.6; SizeY_mm: 0.8; EIA_Code: E96; U/M: EA; AEC Category: Q200; Green_Lifecycle: Active; Green_REACh: Passed
R207 R214 = CMP-0120043-1: 10 kOhms ±1% 0.1W, 1/10W Chip Resistor 0402 (1005 Metric) Anti-Sulfur, Automotive AEC-Q200 Thick Film; Manufacturer: Panasonic; AEC Grade: Grade 0; AEC Qualified: Yes; Power_W: 100mW; SizeZ_mm: 0.4mm; TempCo: 200ppm/°C; VDC_V: 50V; Value: 10k
R208 R216 = CMP-0026329-2: RES, 3.01 k, 1%, 0.063 W, AEC-Q200 Grade 0, 0402; Manufacturer: Vishay-Dale; Power_W: 63mW; TempCo: 100 ppm/C; Value_Code: 3k01; Value: 3.01k; EIA_Code: E96; SizeX_mm: 1; SizeY_mm: 0.5; SizeZ_mm: 0.6; Value2: 0.063W; AEC Qualified: Y; VDC_V: 50V; AEC Category: Q200; AEC Grade: 0
R209 = CMP-0023162-4: RES, 510 k, 1%, 0.1 W, 0603; Manufacturer: Yageo; Power_W: 100mW; TempCo: 100 ppm/C; Value: 510k; SizeX_mm: 1.6; SizeY_mm: 0.8; SizeZ_mm: 1; Value2: 0.1W; SizeArea_mm2: 1.28; AEC Qualified: N; VDC_V: 75V; AEC Category: Q200; SizeAreaWB_mm2: 4.68
R215 = CMP-0026336-2: RES, 3.57 k, 1%, 0.063 W, AEC-Q200 Grade 0, 0402; Manufacturer: Vishay-Dale; Power_W: 63mW; TempCo: 100 ppm/C; Value_Code: 3k57; Value: 3.57k; EIA_Code: E96; SizeX_mm: 1; SizeY_mm: 0.5; SizeZ_mm: 0.6; Value2: 0.063W; AEC Qualified: Y; VDC_V: 50V; AEC Category: Q200; AEC Grade: 0
R217 = CMP-0026668-1: RES, 1.50 k, 1%, 0.1 W, AEC-Q200 Grade 0, 0402; Manufacturer: Panasonic; Power_W: 100mW; TempCo: 100 ppm/C; Value_Code: 1k50; U/M: EA; Value: 1.50k; EIA_Code: E96; Res_ohm: 1.5k; SizeX_mm: 1; SizeY_mm: 0.5; SizeZ_mm: 0.6; Value2: 0.1W; AEC Qualified: Y; VDC_V: 50V; AEC Grade: 0; AEC Category: Q200
R218 R223 R231 R234 = CMP-0026906-3: RES, 330, 5%, 0.063 W, AEC-Q200 Grade 0, 0402; Manufacturer: Vishay-Dale; Power_W: 63mW; TempCo: 200 ppm/C; Value_Code: 330R; Value: 330; EIA_Code: E24; SizeX_mm: 1; SizeY_mm: 0.5; SizeZ_mm: 0.6; Value2: 0.063W; AEC Qualified: Y; VDC_V: 50V; AEC Category: Q200; AEC Grade: 0
R219 R230 = CMP-0089152-1: 100 Ohms ±1% 0.125W, 1/8W Chip Resistor 0603 (1608 Metric) Automotive AEC-Q200, Moisture Resistant Thick Film; Manufacturer: KOA Speer; Approved Alternate Part Number: 541-1.00HHCT-ND; Power_W: 100mW; VDC_V: 75V; TempCo: 100ppm/°C; SizeZ_mm: 0.5mm; AEC Qualified: Yes; AEC Grade: Grade 0; Standoff Height: 0mm
R220 R222 R224 R225 = CRCW060328K7FKEA: RES, 28.7 k, 1%, 0.1 W, 0603; Manufacturer: Vishay-Dale; CompType: Resistor; Value: 28.7k; Res_ohm: 28700; Value_Code: 28k7; Tolerance_%: 1; Power_W: 0.1; Value2: 0.1W; VDC_V: 75; TempCo: 100 ppm/C; SizeArea_mm2: 1.28; SizeX_mm: 1.6; SizeY_mm: 0.8; EIA_Code: E96; U/M: EA; AEC Category: Q200
R221 R226 = CMP-0022973-5: RES, 28.7 k, 1%, 0.1 W, 0603; Manufacturer: Yageo; Value: 28.7k; Value_Code: 28k7; Power_W: 100mW; Value2: 0.1W; VDC_V: 75V; TempCo: 100 ppm/C; SizeArea_mm2: 1.28; SizeX_mm: 1.6; SizeY_mm: 0.8; SizeZ_mm: 1; EIA_Code: E96; AEC Category: Q200; AEC Qualified: N; SizeAreaWB_mm2: 4.68
R227 = CRCW06033K01FKEA: RES, 3.01 k, 1%, 0.1 W, 0603; Manufacturer: Vishay-Dale; CompType: Resistor; Value: 3.01k; Res_ohm: 3010; Value_Code: 3k01; Tolerance_%: 1; Power_W: 0.1; Value2: 0.1W; VDC_V: 75; TempCo: 100 ppm/C; SizeArea_mm2: 1.28; SizeX_mm: 1.6; SizeY_mm: 0.8; EIA_Code: E96; U/M: EA; AEC Category: Q200; Green_Lifecycle: Active; Green_REACh: Passed
R228 R229 = CMP-0024186-3: RES, 3.01 k, 0.1%, 0.1 W, 0603; Manufacturer: Yageo America; Value: 3.01k; Value_Code: 3k01; Power_W: 100mW; Value2: 0.1W; VDC_V: 75V; TempCo: 25 ppm/C; SizeArea_mm2: 1.28; SizeX_mm: 1.6; SizeY_mm: 0.8; SizeZ_mm: 1; EIA_Code: E192; U/M: EA; AEC Category: Q200
R232 R233 R270 R271 = CMP-0120804-1: as R306 on sheet PMP41155_Main
U200 = CMP-0093655-2: -4-V to 110-V, Bidirectional, 1-MHz, 5V/μs, Ultra-Precise Current Sense Amplifier, SOT23-8; Manufacturer: Texas Instruments; CompType: IC; Number Of Channels: 1; Nominal Supply Current: 2.5mA; Input Bias Current: 40uA; Max Supply Voltage: 20V; Voltage Gain: 0.1V/mV; TJmax_C: +150°C; TaMax_C: +125°C; TaMin_C: -40°C; Standoff Height: 0mm; Input Offset Voltage: 0.002mV; AEC Qualified: No; Bandwidth: 1MHz; AEC Category: Q200; Response Time: 1.5us; Min Supply Voltage: 2.7V; SizeZ_mm: 1.1mm
U201 = CMP-0124506-1: Automotive, High-Voltage, Precision, Rail-to-Rail In, Rail-to-Rail Out Op Amp; Manufacturer: Texas Instruments; SizeZ_mm: 1.1mm; AEC Qualified: Yes; AEC Grade: Grade 1; Gain Bandwidth: 10MHz; Input Bias Current: 5pA; Input Offset Voltage: 5uV; Max Dual Supply Voltage: 18V; Max Supply Voltage: 36V; Min Dual Supply Voltage: 2.25V; Min Supply Voltage: 4.5V; Nominal Supply Current: 1mA; Number Of Channels: 2; Output Current Per Channel: 65mA; Response Time: 2.1us; Standoff Height: 0.05mm; TaMax_C: +125°C; TaMin_C: -40°C; TJmax_C: +150°C; Voltage Gain: 140dB
U202 = CMP-0093654-2: -4-V to 110-V, Bidirectional, 1-MHz, 5V/μs, Ultra-Precise Current Sense Amplifier, SOT23-8; Manufacturer: Texas Instruments; Voltage Gain: 0.05V/mV; SizeZ_mm: 1.1mm; Nominal Supply Current: 2.5mA; AEC Category: Q200; Bandwidth: 1MHz; Standoff Height: 0mm; TaMin_C: -40°C; Input Bias Current: 40uA; TaMax_C: +125°C; Min Supply Voltage: 2.7V; Input Offset Voltage: 0.002mV; Number Of Channels: 1; AEC Qualified: No; CompType: IC; Response Time: 1.5us; Max Supply Voltage: 20V; TJmax_C: +150°C
U204 = CMP-0013007-4: 10-MHz, Low-Noise, RRIO, CMOS Operational Amplifier for Cost-Sensitive Systems, D0008A (SOIC-8); Manufacturer: Texas Instruments; SizeX_mm: 4.9; SizeY_mm: 6.2; CompType: IC; SizeZ_mm: 1.75; SizeArea_mm2: 30.38; SizeAreaWB_mm2: 56.58; AEC Category: Q200; AEC Qualified: N; Rating: Catalog

## Sheet PMP41155_Main_Control 1.SchDoc
size 431 x 279 mm; Date: Not shown in title block; ApprovedBy: Not shown in title block; CheckedBy: Not shown in title block; Author: Not shown in title block; CompanyName: Not shown in title block; Engineer: Not shown in title block; Organization: Not shown in title block; Address1: Not shown in title block; Address2: Not shown in title block; Address3: Not shown in title block; Address4: Not shown in title block; DocumentNumber: 3; Revision: Use project parameter SCH_Rev; SheetNumber: 3; SheetTotal: 5; PageSetup: Record=PageOptions¦CenterHorizontal=True¦CenterVertical=True¦PrintScale=1.00¦XCorrection=1.00¦YCorrection=1.00¦PrintKind=0¦BorderSize=5000000¦LeftOffset=0¦BottomOffset=0¦Orientation=2¦PaperLength=1000¦PaperWidth=1000¦Scale=100¦PaperSource=15¦PrintQuality=600¦MediaType=1¦DitherType=10¦PaperKind=Letter¦PrintScaleMode=1
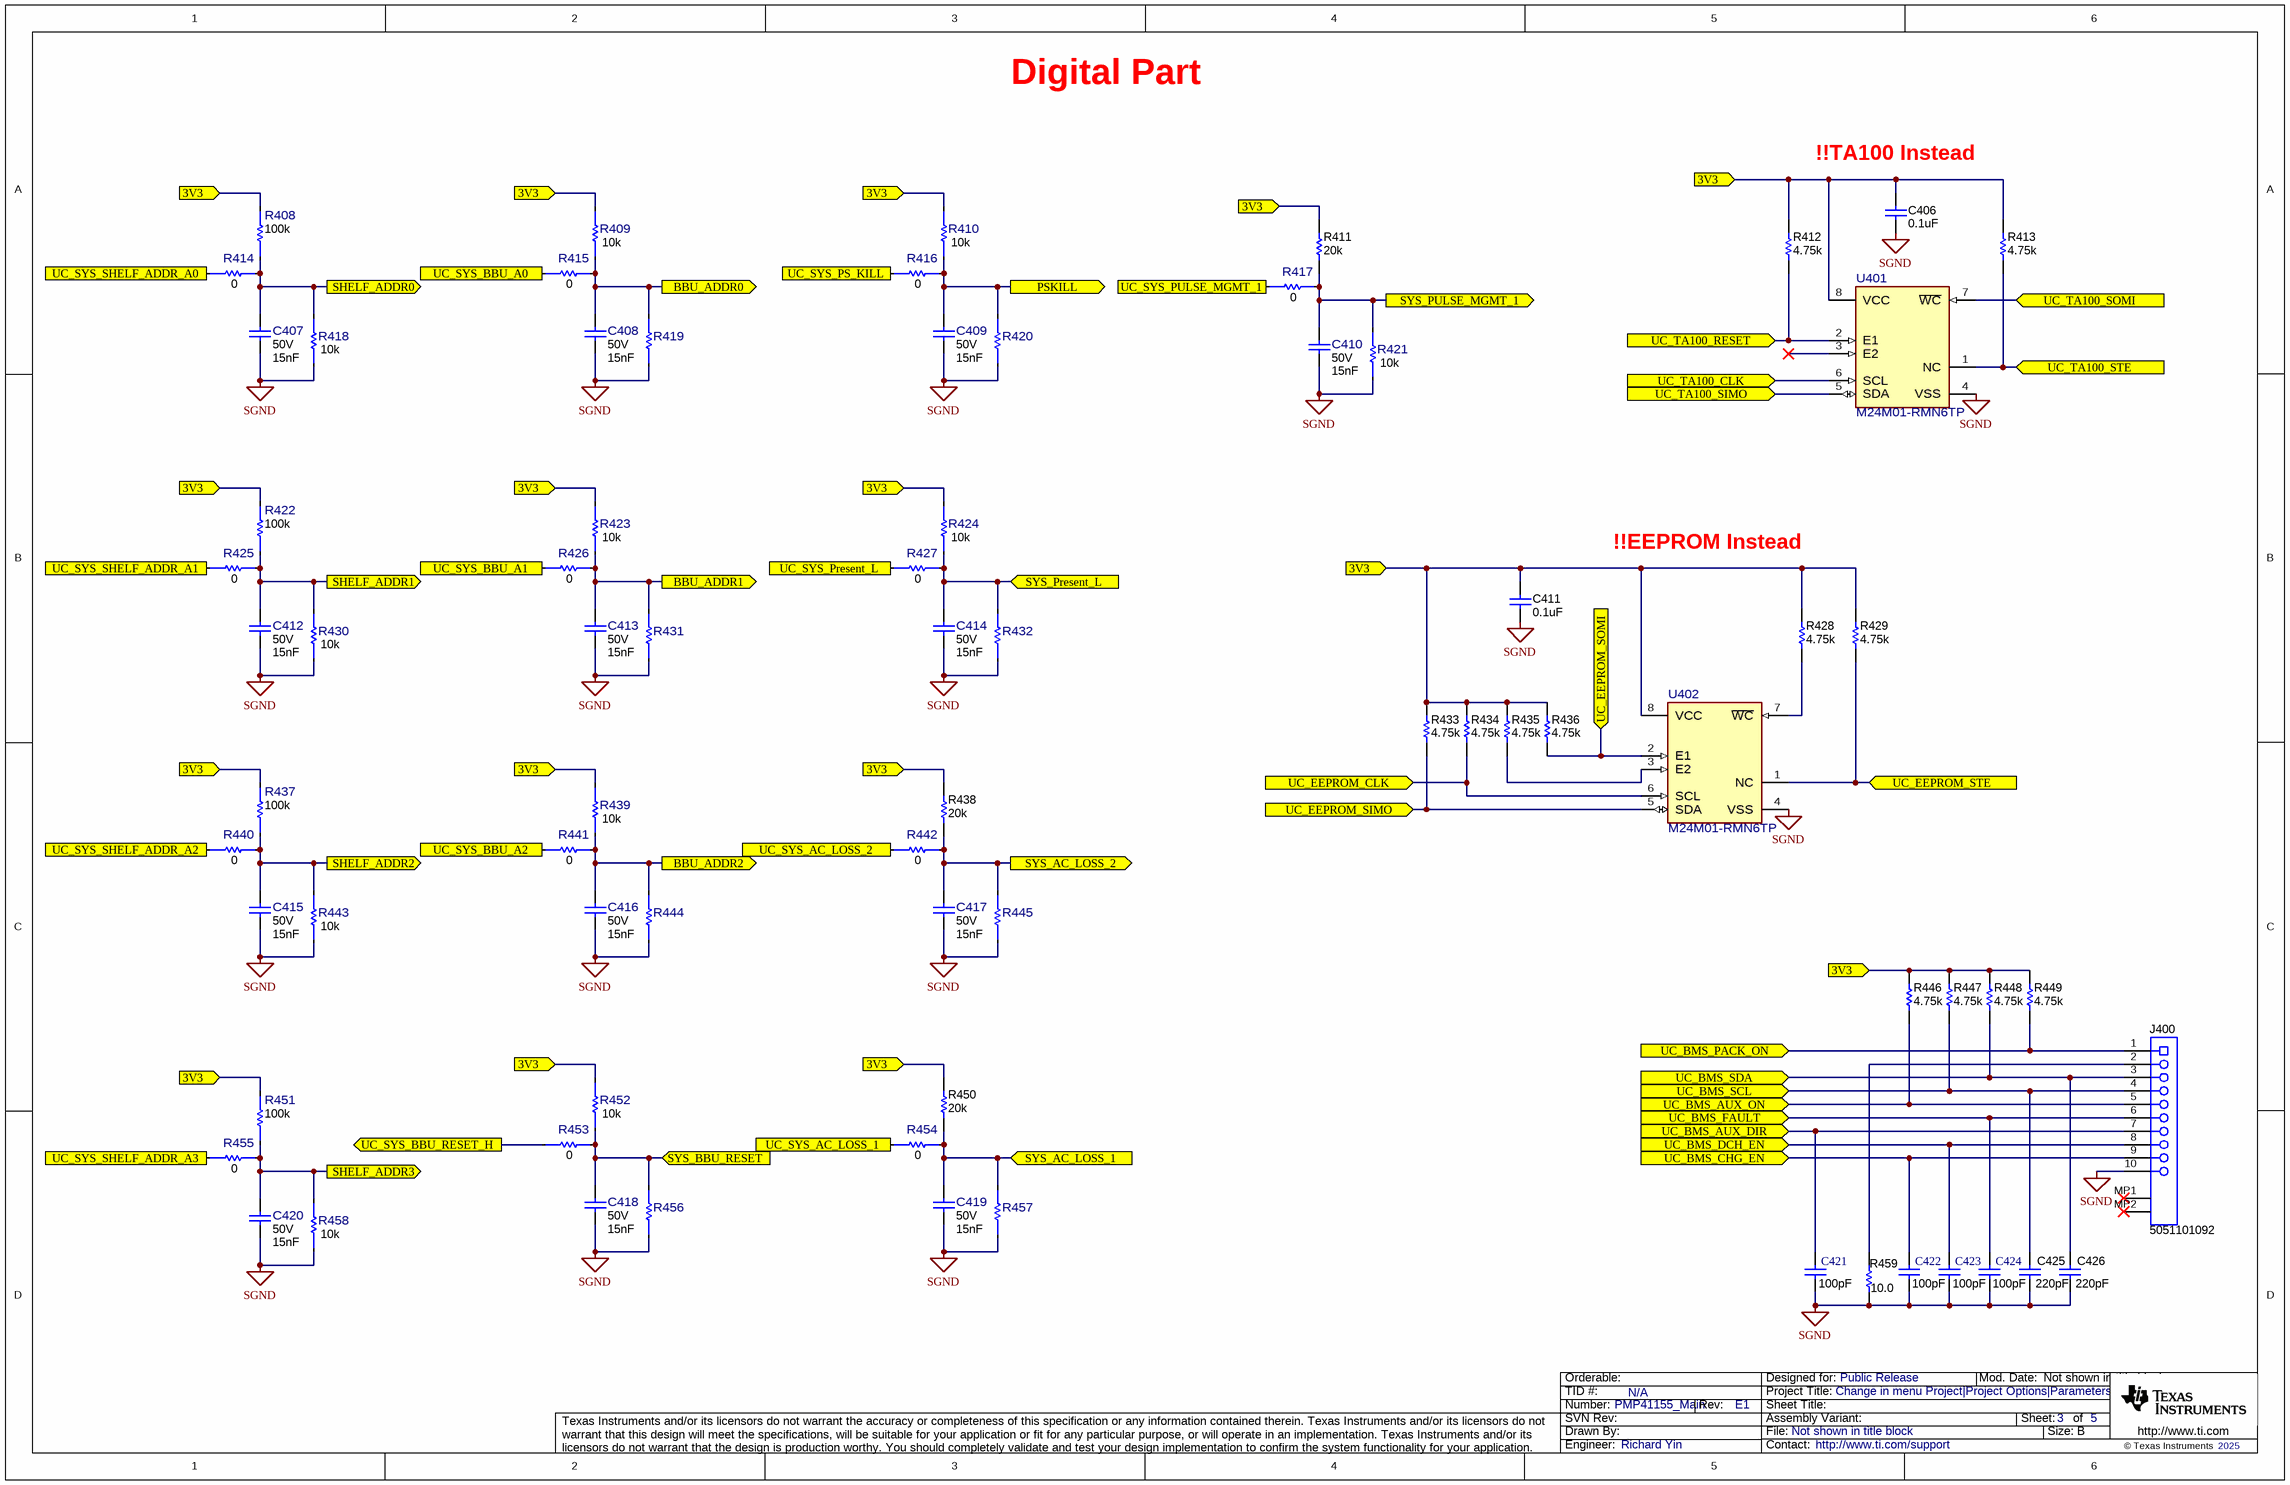
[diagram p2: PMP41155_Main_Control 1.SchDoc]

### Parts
C406  ValueDisplayed: 0.1uF  [0402]  (hidden comment: CMP-0006623-2)
C407  VDC_V: 50V  Cap_F: 15nF  [FP-C0603C153K5RACTU_0603-IPC_A]  (hidden comment: C0603C153K5RACTU)
C408  VDC_V: 50V  Cap_F: 15nF  [FP-C0603C153K5RACTU_0603-IPC_A]  (hidden comment: C0603C153K5RACTU)
C409  VDC_V: 50V  Cap_F: 15nF  [FP-C0603C153K5RACTU_0603-IPC_A]  (hidden comment: C0603C153K5RACTU)
C410  VDC_V: 50V  Cap_F: 15nF  [FP-C0603C153K5RACTU_0603-IPC_A]  (hidden comment: C0603C153K5RACTU)
C411  ValueDisplayed: 0.1uF  [0402]  (hidden comment: CMP-0006623-2)
C412  VDC_V: 50V  Cap_F: 15nF  [FP-C0603C153K5RACTU_0603-IPC_A]  (hidden comment: C0603C153K5RACTU)
C413  VDC_V: 50V  Cap_F: 15nF  [FP-C0603C153K5RACTU_0603-IPC_A]  (hidden comment: C0603C153K5RACTU)
C414  VDC_V: 50V  Cap_F: 15nF  [FP-C0603C153K5RACTU_0603-IPC_A]  (hidden comment: C0603C153K5RACTU)
C415  VDC_V: 50V  Cap_F: 15nF  [FP-C0603C153K5RACTU_0603-IPC_A]  (hidden comment: C0603C153K5RACTU)
C416  VDC_V: 50V  Cap_F: 15nF  [FP-C0603C153K5RACTU_0603-IPC_A]  (hidden comment: C0603C153K5RACTU)
C417  VDC_V: 50V  Cap_F: 15nF  [FP-C0603C153K5RACTU_0603-IPC_A]  (hidden comment: C0603C153K5RACTU)
C418  VDC_V: 50V  Cap_F: 15nF  [FP-C0603C153K5RACTU_0603-IPC_A]  (hidden comment: C0603C153K5RACTU)
C419  VDC_V: 50V  Cap_F: 15nF  [FP-C0603C153K5RACTU_0603-IPC_A]  (hidden comment: C0603C153K5RACTU)
C420  VDC_V: 50V  Cap_F: 15nF  [FP-C0603C153K5RACTU_0603-IPC_A]  (hidden comment: C0603C153K5RACTU)
C421  Cap_F: 100pF  [WCAP-CSGP_0402_L1W0.5H0.5]  (hidden comment: 885012205001)
C422  Cap_F: 100pF  [WCAP-CSGP_0402_L1W0.5H0.5]  (hidden comment: 885012205001)
C423  Cap_F: 100pF  [WCAP-CSGP_0402_L1W0.5H0.5]  (hidden comment: 885012205001)
C424  Cap_F: 100pF  [WCAP-CSGP_0402_L1W0.5H0.5]  (hidden comment: 885012205001)
C425  ValueDisplayed: 220pF  [0603]  (hidden comment: C0603X221K5RACTU)
C426  ValueDisplayed: 220pF  [0603]  (hidden comment: C0603X221K5RACTU)
J400  5051101092  [Molex_5051101092]
R408  Res_ohm: 100k  [FP-RC0402JR-07100KL_0402-MFG]  (hidden comment: RC0402JR-07100KL)
R409  Res_ohm: 10k  [FP-ERJ-U02F1002X_0402-MFG]  (hidden comment: ERJ-U02F1002X)
R410  Res_ohm: 10k  [FP-ERJ-U02F1002X_0402-MFG]  (hidden comment: ERJ-U02F1002X)
R411  ValueDisplayed: 20k  [0402]  (hidden comment: ERJ-2GEJ203X)
R412  ValueDisplayed: 4.75k  [0603]  (hidden comment: RC0603FR-074K75L)
R413  ValueDisplayed: 4.75k  [0603]  (hidden comment: RC0603FR-074K75L)
R414  Res_ohm: 0  [FP-JR0805X35E_0805-MFG]  (hidden comment: JR0805X35E)
R415  Res_ohm: 0  [FP-JR0805X35E_0805-MFG]  (hidden comment: JR0805X35E)
R416  Res_ohm: 0  [FP-JR0805X35E_0805-MFG]  (hidden comment: JR0805X35E)
R417  Res_ohm: 0  [FP-JR0805X35E_0805-MFG]  (hidden comment: JR0805X35E)
R418  Res_ohm: 10k  [FP-ERJ-U02F1002X_0402-MFG]  (hidden comment: ERJ-U02F1002X)
R419  ERJ-U02F1002X  [FP-ERJ-U02F1002X_0402-MFG]  (value not drawn)
R420  ERJ-U02F1002X  [FP-ERJ-U02F1002X_0402-MFG]  (value not drawn)
R421  Res_ohm: 10k  [FP-ERJ-U02F1002X_0402-MFG]  (hidden comment: ERJ-U02F1002X)
R422  Res_ohm: 100k  [FP-RC0402JR-07100KL_0402-MFG]  (hidden comment: RC0402JR-07100KL)
R423  Res_ohm: 10k  [FP-ERJ-U02F1002X_0402-MFG]  (hidden comment: ERJ-U02F1002X)
R424  Res_ohm: 10k  [FP-ERJ-U02F1002X_0402-MFG]  (hidden comment: ERJ-U02F1002X)
R425  Res_ohm: 0  [FP-JR0805X35E_0805-MFG]  (hidden comment: JR0805X35E)
R426  Res_ohm: 0  [FP-JR0805X35E_0805-MFG]  (hidden comment: JR0805X35E)
R427  Res_ohm: 0  [FP-JR0805X35E_0805-MFG]  (hidden comment: JR0805X35E)
R428  ValueDisplayed: 4.75k  [0603]  (hidden comment: RC0603FR-074K75L)
R429  ValueDisplayed: 4.75k  [0603]  (hidden comment: RC0603FR-074K75L)
R430  Res_ohm: 10k  [FP-ERJ-U02F1002X_0402-MFG]  (hidden comment: ERJ-U02F1002X)
R431  ERJ-U02F1002X  [FP-ERJ-U02F1002X_0402-MFG]  (value not drawn)
R432  ERJ-U02F1002X  [FP-ERJ-U02F1002X_0402-MFG]  (value not drawn)
R433  ValueDisplayed: 4.75k  [0603]  (hidden comment: RC0603FR-074K75L)
R434  ValueDisplayed: 4.75k  [0603]  (hidden comment: RC0603FR-074K75L)
R435  ValueDisplayed: 4.75k  [0603]  (hidden comment: RC0603FR-074K75L)
R436  ValueDisplayed: 4.75k  [0603]  (hidden comment: RC0603FR-074K75L)
R437  Res_ohm: 100k  [FP-RC0402JR-07100KL_0402-MFG]  (hidden comment: RC0402JR-07100KL)
R438  ValueDisplayed: 20k  [0402]  (hidden comment: ERJ-2GEJ203X)
R439  Res_ohm: 10k  [FP-ERJ-U02F1002X_0402-MFG]  (hidden comment: ERJ-U02F1002X)
R440  Res_ohm: 0  [FP-JR0805X35E_0805-MFG]  (hidden comment: JR0805X35E)
R441  Res_ohm: 0  [FP-JR0805X35E_0805-MFG]  (hidden comment: JR0805X35E)
R442  Res_ohm: 0  [FP-JR0805X35E_0805-MFG]  (hidden comment: JR0805X35E)
R443  Res_ohm: 10k  [FP-ERJ-U02F1002X_0402-MFG]  (hidden comment: ERJ-U02F1002X)
R444  ERJ-U02F1002X  [FP-ERJ-U02F1002X_0402-MFG]  (value not drawn)
R445  ERJ-U02F1002X  [FP-ERJ-U02F1002X_0402-MFG]  (value not drawn)
R446  ValueDisplayed: 4.75k  [0603]  (hidden comment: RC0603FR-074K75L)
R447  ValueDisplayed: 4.75k  [0603]  (hidden comment: RC0603FR-074K75L)
R448  ValueDisplayed: 4.75k  [0603]  (hidden comment: RC0603FR-074K75L)
R449  ValueDisplayed: 4.75k  [0603]  (hidden comment: RC0603FR-074K75L)
R450  ValueDisplayed: 20k  [0402]  (hidden comment: ERJ-2GEJ203X)
R451  Res_ohm: 100k  [FP-RC0402JR-07100KL_0402-MFG]  (hidden comment: RC0402JR-07100KL)
R452  Res_ohm: 10k  [FP-ERJ-U02F1002X_0402-MFG]  (hidden comment: ERJ-U02F1002X)
R453  Res_ohm: 0  [FP-JR0805X35E_0805-MFG]  (hidden comment: JR0805X35E)
R454  Res_ohm: 0  [FP-JR0805X35E_0805-MFG]  (hidden comment: JR0805X35E)
R455  Res_ohm: 0  [FP-JR0805X35E_0805-MFG]  (hidden comment: JR0805X35E)
R456  ERJ-U02F1002X  [FP-ERJ-U02F1002X_0402-MFG]  (value not drawn)
R457  ERJ-U02F1002X  [FP-ERJ-U02F1002X_0402-MFG]  (value not drawn)
R458  Res_ohm: 10k  [FP-ERJ-U02F1002X_0402-MFG]  (hidden comment: ERJ-U02F1002X)
R459  ValueDisplayed: 10.0  [0402]  (hidden comment: MCR01MZPF10R0)
U401  M24M01-RMN6TP  [FP-M24M01-RMN6TP_SOIC8-MFG]
U402  M24M01-RMN6TP  [FP-M24M01-RMN6TP_SOIC8-MFG]

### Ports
3V3 (in), BBU_ADDR0 (out), BBU_ADDR1 (out), BBU_ADDR2 (out), PSKILL (out), SHELF_ADDR0 (out), SHELF_ADDR1 (out), SHELF_ADDR2 (out), SHELF_ADDR3 (out), SYS_AC_LOSS_1 (in), SYS_AC_LOSS_2 (out), SYS_BBU_RESET (in), SYS_Present_L (in), SYS_PULSE_MGMT_1 (out), UC_BMS_AUX_DIR (in), UC_BMS_AUX_ON (in), UC_BMS_CHG_EN (in), UC_BMS_DCH_EN (in), UC_BMS_FAULT (in), UC_BMS_PACK_ON (in), UC_BMS_SCL (in), UC_BMS_SDA (in), UC_EEPROM_CLK (in), UC_EEPROM_SIMO (in), UC_EEPROM_SOMI (in), UC_EEPROM_STE (in), UC_SYS_AC_LOSS_1 (out), UC_SYS_AC_LOSS_2 (in), UC_SYS_BBU_A0 (out), UC_SYS_BBU_A1 (out), UC_SYS_BBU_A2 (out), UC_SYS_BBU_RESET_H (out), UC_SYS_Present_L (out), UC_SYS_PS_KILL (in), UC_SYS_PULSE_MGMT_1 (in), UC_SYS_SHELF_ADDR_A0 (out), UC_SYS_SHELF_ADDR_A1 (out), UC_SYS_SHELF_ADDR_A2 (out), UC_SYS_SHELF_ADDR_A3 (out), UC_TA100_CLK (in), UC_TA100_RESET (in), UC_TA100_SIMO (in), UC_TA100_SOMI (in), UC_TA100_STE (in)

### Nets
SGND: C406.2 C407.2 C408.2 C409.2 C410.2 C411.2 C412.2 C413.2 C414.2 C415.2 C416.2 C417.2 C418.2 C419.2 C420.2 C421.1 C422.1 C423.1 C424.1 C425.1 C426.1 J400.10 R418.1 R419.1 R420.1 R421.1 R430.1 R431.1 R432.1 R443.1 R444.1 R445.1 R456.1 R457.1 R458.1 R459.1 U401.4(VSS) U402.4(VSS)
3V3: C406.1 C411.1 R408.2 R409.2 R410.2 R411.2 R412.2 R413.2 R422.2 R423.2 R424.2 R428.2 R429.2 R433.2 R434.2 R435.2 R436.2 R437.2 R438.2 R439.2 R446.2 R447.2 R448.2 R449.2 R450.2 R451.2 R452.2 U401.8(VCC) U402.8(VCC) ; port 3V3
BBU_ADDR0: C408.1 R409.1 R415.2 R419.2 ; port BBU_ADDR0
BBU_ADDR1: C413.1 R423.1 R426.2 R431.2 ; port BBU_ADDR1
BBU_ADDR2: C416.1 R439.1 R441.2 R444.2 ; port BBU_ADDR2
PSKILL: C409.1 R410.1 R416.2 R420.2 ; port PSKILL
SHELF_ADDR0: C407.1 R408.1 R414.2 R418.2 ; port SHELF_ADDR0
SHELF_ADDR1: C412.1 R422.1 R425.2 R430.2 ; port SHELF_ADDR1
SHELF_ADDR2: C415.1 R437.1 R440.2 R443.2 ; port SHELF_ADDR2
SHELF_ADDR3: C420.1 R451.1 R455.2 R458.2 ; port SHELF_ADDR3
SYS_AC_LOSS_1: C419.1 R450.1 R454.2 R457.2 ; port SYS_AC_LOSS_1
SYS_AC_LOSS_2: C417.1 R438.1 R442.2 R445.2 ; port SYS_AC_LOSS_2
SYS_BBU_RESET: C418.1 R452.1 R453.2 R456.2 ; port SYS_BBU_RESET
SYS_Present_L: C414.1 R424.1 R427.2 R432.2 ; port SYS_Present_L
SYS_PULSE_MGMT_1: C410.1 R411.1 R417.2 R421.2 ; port SYS_PULSE_MGMT_1
UC_BMS_AUX_DIR: C421.2 J400.7 ; port UC_BMS_AUX_DIR
UC_BMS_AUX_ON: J400.5 R446.1 ; port UC_BMS_AUX_ON
UC_BMS_CHG_EN: C422.2 J400.9 ; port UC_BMS_CHG_EN
UC_BMS_DCH_EN: C423.2 J400.8 ; port UC_BMS_DCH_EN
UC_BMS_FAULT: C424.2 J400.6 ; port UC_BMS_FAULT
UC_BMS_PACK_ON: J400.1 R449.1 ; port UC_BMS_PACK_ON
UC_BMS_SCL: C425.2 J400.4 R447.1 ; port UC_BMS_SCL
UC_BMS_SDA: C426.2 J400.3 R448.1 ; port UC_BMS_SDA
UC_EEPROM_CLK: R434.1 U402.6(SCL) ; port UC_EEPROM_CLK
UC_EEPROM_SIMO: R433.1 U402.5(SDA) ; port UC_EEPROM_SIMO
UC_EEPROM_SOMI: R436.1 U402.2(E1) ; port UC_EEPROM_SOMI
UC_EEPROM_STE: R429.1 U402.1(NC) ; port UC_EEPROM_STE
UC_SYS_AC_LOSS_1: R454.1 ; port UC_SYS_AC_LOSS_1
UC_SYS_AC_LOSS_2: R442.1 ; port UC_SYS_AC_LOSS_2
UC_SYS_BBU_A0: R415.1 ; port UC_SYS_BBU_A0
UC_SYS_BBU_A1: R426.1 ; port UC_SYS_BBU_A1
UC_SYS_BBU_A2: R441.1 ; port UC_SYS_BBU_A2
UC_SYS_BBU_RESET_H: R453.1 ; port UC_SYS_BBU_RESET_H
UC_SYS_Present_L: R427.1 ; port UC_SYS_Present_L
UC_SYS_PS_KILL: R416.1 ; port UC_SYS_PS_KILL
UC_SYS_PULSE_MGMT_1: R417.1 ; port UC_SYS_PULSE_MGMT_1
UC_SYS_SHELF_ADDR_A0: R414.1 ; port UC_SYS_SHELF_ADDR_A0
UC_SYS_SHELF_ADDR_A1: R425.1 ; port UC_SYS_SHELF_ADDR_A1
UC_SYS_SHELF_ADDR_A2: R440.1 ; port UC_SYS_SHELF_ADDR_A2
UC_SYS_SHELF_ADDR_A3: R455.1 ; port UC_SYS_SHELF_ADDR_A3
UC_TA100_CLK: U401.6(SCL) ; port UC_TA100_CLK
UC_TA100_RESET: R412.1 U401.2(E1) ; port UC_TA100_RESET
UC_TA100_SIMO: U401.5(SDA) ; port UC_TA100_SIMO
UC_TA100_SOMI: U401.7(~{WC}) ; port UC_TA100_SOMI
UC_TA100_STE: R413.1 U401.1(NC) ; port UC_TA100_STE
NetJ400_2: J400.2 R459.2
NetR428_1: R428.1 U402.7(~{WC})
NetR435_1: R435.1 U402.3(E2)

Not connected (* = marked no-connect by the designer): J400 MP1* MP2*; U401 3(E2)*

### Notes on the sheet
- Digital Part
- (near C406) !!TA100 Instead
- !!EEPROM Instead

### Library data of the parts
C406 C411 = CMP-0006623-2: CAP, CERM, 0.1 uF, 6.3 V, +/- 10%, X7R, 0402; PartNumber: GRM155R70J104KA01D; Manufacturer: MuRata; Polarized: N; Value: 0.1uF; U/M: EA; Cap_F: 100nF; Value1: Unknown; VDC_V: 6.3V; TaMin_C: -55°C; TaMax_C: 125°C; SizeAreaWB_mm2: 3; SizeZ_mm: 0.6; SizeX_mm: 1; SizeY_mm: 0.5; AEC Category: Q200
C407-C410 C412-C420 = CMP-0086419-2: Cap Ceramic 0.015uF 50V X7R 10% Pad SMD 0603 125°C T/R; Manufacturer: Kemet; SizeZ_mm: 0.87mm; AEC Qualified: No; TempCo: 15%; Symbol Name: SYM-C0603C153K5RACTU
C421-C424 = CMP-0115312-1: WCAP-CSGP Multilayer Ceramic Chip Capacitor, General Purpose, size 0402, X7R, 100pF, 10VDC; Manufacturer: Wurth Elektronik; Capacitance Tolerance: +/-10%; Case/Size Code: 0402; Dissipation Factor: 5%; Insulation Resistance: 10GOhm; Rated Voltage (DC): 10V; Technical Reference: X7R0402101K010DFCT10000
C425 C426 = CMP-0006982-4: CAP, CERM, 220 pF, 50 V, +/- 10%, X7R, 0603; Manufacturer: Kemet; Polarized: N; Value: 220pF; U/M: EA; Value1: Unknown; VDC_V: 50V; TaMin_C: -55°C; TaMax_C: 125°C; SizeArea_mm2: 1.28; SizeAreaWB_mm2: 4.68; SizeX_mm: 1.6; SizeY_mm: 0.8; SizeZ_mm: 1; AEC Category: Q200
J400 = CMP-0082591-1: FPC Connector, 0.5mm, 10 Pos, R/A, SMT; Manufacturer: Molex; Pitch_mm: 0.5; Gender: Female; Cert_UL: Y; Voltage_V: 50V; Current_A: 500mA; ContactFinish: Gold; Row_Count: 1; CompType: FFC or FPC
R408 R422 R437 R451 = CMP-0094182-1: 100 kOhms ±5% 0.063W, 1/16W Chip Resistor 0402 (1005 Metric) Moisture Resistant Thick Film; Manufacturer: YAGEO; Power_W: 63mW; AEC Qualified: No; TempCo: 100ppm/°C; Value: 100k; VDC_V: 50V; SizeZ_mm: 0.4mm
R409 R410 R418 R421 R423 R424 R430 R439 R443 R452 R458 = CMP-0120043-1: as R207 on sheet PMP41155_Main_Control 2
R411 R438 R450 = CMP-0026996-2: RES, 20 k, 5%, 0.1 W, AEC-Q200 Grade 0, 0402; Manufacturer: Panasonic; Power_W: 100mW; TempCo: 200 ppm/C; Value_Code: 20k0; U/M: EA; Value: 20k; EIA_Code: E24; SizeX_mm: 1; SizeY_mm: 0.5; SizeZ_mm: 0.6; Value2: 0.1W; AEC Qualified: Y; VDC_V: 50V; AEC Grade: 0; AEC Category: Q200
R412 R413 R428 R429 R433-R436 R446-R449 = CMP-0023152-5: RES, 4.75 k, 1%, 0.1 W, 0603; Manufacturer: Yageo; Value: 4.75k; Value_Code: 4k75; Power_W: 100mW; Value2: 0.1W; VDC_V: 75V; TempCo: 100 ppm/C; SizeArea_mm2: 1.28; SizeX_mm: 1.6; SizeY_mm: 0.8; SizeZ_mm: 1; EIA_Code: E96; AEC Category: Q200; AEC Qualified: N; SizeAreaWB_mm2: 4.68
R414-R417 R425-R427 R440-R442 R453-R455 = CMP-0096818-1: 0 Ohms Jumper 0.245W Chip Resistor 0805 (2012 Metric) - Metal Element; Manufacturer: Ohmite; AEC Qualified: No; Value: 0; Power_W: 245mW; SizeZ_mm: 0.55mm
R419 R420 R431 R432 R444 R445 R456 R457 = CMP-0120043-1: 10 kOhms ±1% 0.1W, 1/10W Chip Resistor 0402 (1005 Metric) Anti-Sulfur, Automotive AEC-Q200 Thick Film; Manufacturer: Panasonic; AEC Grade: Grade 0; AEC Qualified: Yes; Power_W: 100mW; Res_ohm: 10k; SizeZ_mm: 0.4mm; TempCo: 200ppm/°C; VDC_V: 50V; Value: 10k
R459 = CMP-0026717-1: as R202 on sheet PMP41155_Main_Control 2
U401 U402 = CMP-0086585-1: IC EEPROM 1M I2C 1MHZ 8SO; Manufacturer: ST Microelectronics; SizeZ_mm: 1.75mm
